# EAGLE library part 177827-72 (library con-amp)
M III Socked 177827.pdf
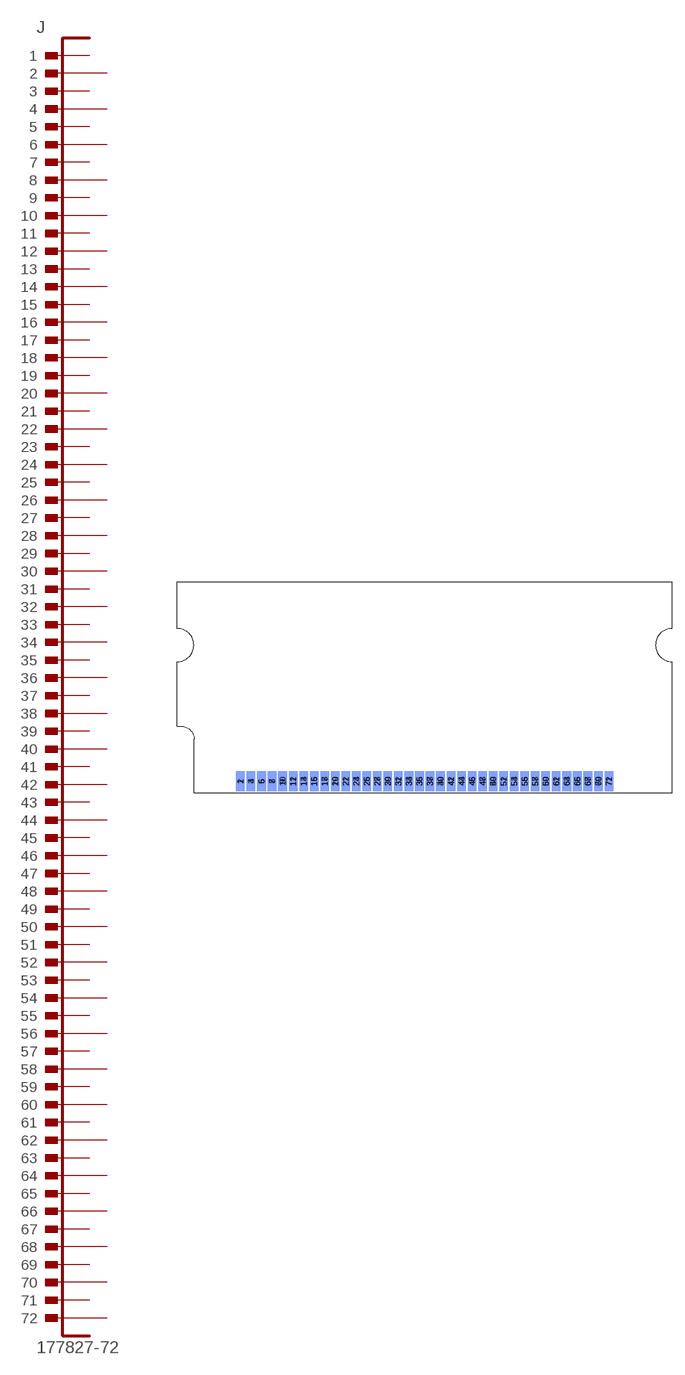
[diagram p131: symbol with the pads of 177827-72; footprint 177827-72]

Designator prefix J

## 177827-72 (OC_FARNELL: unknown; OC_NEWARK: unknown)  [177827-72]
1  1  pas
2  2  pas
3  3  pas
4  4  pas
5  5  pas
6  6  pas
7  7  pas
8  8  pas
9  9  pas
10  10  pas
11  11  pas
12  12  pas
13  13  pas
14  14  pas
15  15  pas
16  16  pas
17  17  pas
18  18  pas
19  19  pas
20  20  pas
21  21  pas
22  22  pas
23  23  pas
24  24  pas
25  25  pas
26  26  pas
27  27  pas
28  28  pas
29  29  pas
30  30  pas
31  31  pas
32  32  pas
33  33  pas
34  34  pas
35  35  pas
36  36  pas
37  37  pas
38  38  pas
39  39  pas
40  40  pas
41  41  pas
42  42  pas
43  43  pas
44  44  pas
45  45  pas
46  46  pas
47  47  pas
48  48  pas
49  49  pas
50  50  pas
51  51  pas
52  52  pas
53  53  pas
54  54  pas
55  55  pas
56  56  pas
57  57  pas
58  58  pas
59  59  pas
60  60  pas
61  61  pas
62  62  pas
63  63  pas
64  64  pas
65  65  pas
66  66  pas
67  67  pas
68  68  pas
69  69  pas
70  70  pas
71  71  pas
72  72  pas

## Footprint 177827-72 (pad centres in mm)
SIMM Modul 177827-72 177827-72.pdf
smd 1.04 x 2.4: 1 -22.225,1.35; 3 -20.955,1.35; 5 -19.685,1.35; 7 -18.415,1.35; 9 -17.145,1.35; 11 -15.875,1.35; 13 -14.605,1.35; 15 -13.335,1.35; 17 -12.065,1.35; 19 -10.795,1.35; 21 -9.525,1.35; 23 -8.255,1.35; 25 -6.985,1.35; 27 -5.715,1.35; 29 -4.445,1.35; 31 -3.175,1.35; 33 -1.905,1.35; 35 -0.635,1.35; 37 0.635,1.35; 39 1.905,1.35; 41 3.175,1.35; 43 4.445,1.35; 45 5.715,1.35; 47 6.985,1.35; 49 8.255,1.35; 51 9.525,1.35; 53 10.795,1.35; 55 12.065,1.35; 57 13.335,1.35; 59 14.605,1.35; 61 15.875,1.35; 63 17.145,1.35; 65 18.415,1.35; 67 19.685,1.35; 69 20.955,1.35; 71 22.225,1.35
smd 1.04 x 2.4 bottom: 2 -22.225,1.35; 4 -20.955,1.35; 6 -19.685,1.35; 8 -18.415,1.35; 10 -17.145,1.35; 12 -15.875,1.35; 14 -14.605,1.35; 16 -13.335,1.35; 18 -12.065,1.35; 20 -10.795,1.35; 22 -9.525,1.35; 24 -8.255,1.35; 26 -6.985,1.35; 28 -5.715,1.35; 30 -4.445,1.35; 32 -3.175,1.35; 34 -1.905,1.35; 36 -0.635,1.35; 38 0.635,1.35; 40 1.905,1.35; 42 3.175,1.35; 44 4.445,1.35; 46 5.715,1.35; 48 6.985,1.35; 50 8.255,1.35; 52 9.525,1.35; 54 10.795,1.35; 56 12.065,1.35; 58 13.335,1.35; 60 14.605,1.35; 62 15.875,1.35; 64 17.145,1.35; 66 18.415,1.35; 68 19.685,1.35; 70 20.955,1.35; 72 22.225,1.35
